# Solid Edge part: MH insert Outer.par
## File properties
Author: Dan
Template: FH Insert .par
Last saved by: Dan
Revision: 34
Application: Solid Edge
Material: Steel
Face Style: Steel
Fill Style: ANSI32(Steel)
Virtual Style: Machined steel
Coef. of Thermal Exp: 1.3e-05
Thermal Conductivity: 32.0
Specific Heat: 481.0
Modulus of Elasticity: 199947953000.0
Poisson's Ratio: 0.29
Yield Stress: 262000766.0
Ultimate Stress: 358527364.0
Elongation: 0.0
Density: 7833.000 kg/m^3
Accuracy: 0.990
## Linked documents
FH insert Outer.par
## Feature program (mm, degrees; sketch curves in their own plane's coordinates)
part copy "CopiedPart_2"
delete holes assoc c "unnamed DeleteHolesAssocC 1"
delete faces "unnamed DeleteFaces 1"
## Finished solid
Body 1: solid body, 107 faces, 216 edges, 116 vertices.
  Faces by surface: plane 76, cylinder 23, cone 5, spun 2, torus 1
  Edges by curve: line 166, circle 50
Bounding box of the edges (mm; curved faces can reach further): 116.000 x 116.000 x 26.842, from (-58, -58, -36) to (58, 58, -9.1581).
Cylindrical faces by radius (mm): R2.4585 x4, R18.8116 x1, R21.8198 x1, R22.25 x1, R26.8948 x1, R31.4973 x1, R35.75 x1, R38.57 x2, R38.8542 x2, R40.75 x1, R45.5 x1, R53 x1, R55.65 x2, R58 x4
Conical faces (half-angle, radius in mm at the cone's reference point): 2 deg R19.3388 x1, 59 deg R2.4585 x4
Toroidal faces (ring radius, tube radius in mm): R20.4107 r1.015 x1
Planar faces by outward normal: +x 14, +y 10, +z 17, -x 10, -y 18, -z 5, oblique 2
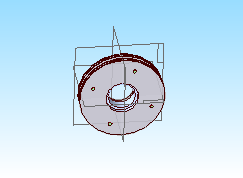
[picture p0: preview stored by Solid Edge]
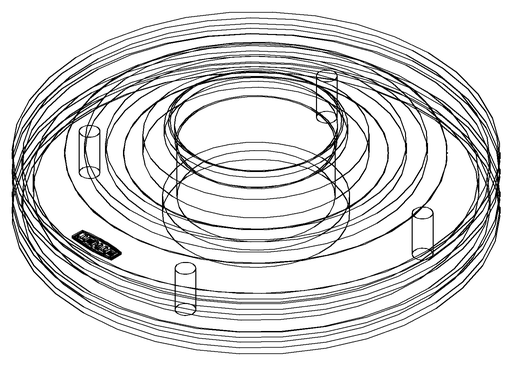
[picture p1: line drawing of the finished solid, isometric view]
